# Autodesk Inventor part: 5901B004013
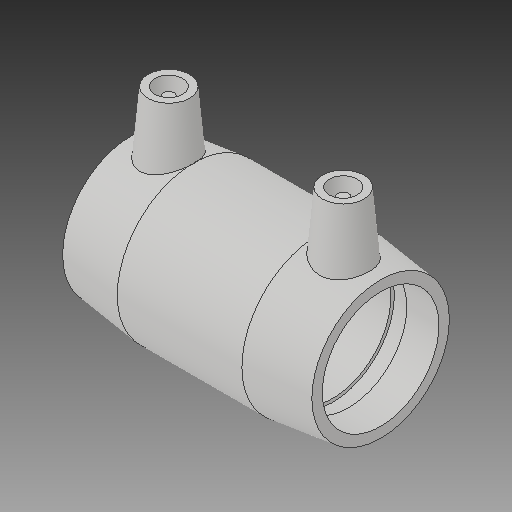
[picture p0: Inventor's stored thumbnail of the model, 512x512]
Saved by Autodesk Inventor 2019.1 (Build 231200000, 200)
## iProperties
Created: 2017-06
Part Number: 5901B004013
Material: Generic
Description: PLASSON IPS COUPLER 1 1/4''
Document SubType Name: Modeling
Designer: KIM
Mass: 8622.19 g
Surface Area: 6772.47 cm^2
Volume: 8622.19 cm^3
Density: 1 g/cm^3
Appearance: Default
Author: KIM
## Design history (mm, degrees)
derived "5901B.ipt"
feature "Solid1::5901B.ipt"
tag "TaggingFeature1"
body "Solid1"
other parameters: "d0" = 89.916, "d1" = 42.1, "d2" = 55.118, "d3" = 43.434, "d4" = 22.479, "d5" = 49.6062, "d6" = 33.68, "d7" = 42.1, "d8" = 168 deg, "d10" = 17.3736, "d11" = 5.7912, "d13" = 89.916, "d14" = 17.6296, "d18" = 42.1, "d19" = 3.52592, "d20" = 168 deg, "d22" = 51.81092, "d23" = 55.118, "d24" = 50.25659, "d25" = 135 deg, "d26" = 40.4622, "d27" = 135 deg, "d29" = 46.99, "d30" = 15, "d31" = 31.4706, "d34" = 5 deg, "d35" = 15, "d39" = 5 deg, "d41" = 4, "d42" = 14, "d43" = 0, "d45" = 4, "d46" = 14, "d47" = 0, "d48" = 3, "d49" = 0, "d50" = 3, "d51" = 0, "d52" = 12.59586, "d53" = 3.14896, "d55" = 43.434, "d_" = 42.1, "L_" = 89.916, "L_1" = 43.434, "D_" = 55.118, "A_" = 46.99, "d_2" = 12, "B_" = 46.99
